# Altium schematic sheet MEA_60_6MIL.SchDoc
size A3; DocumentNumber: 1; SheetNumber: 1; SheetTotal: 1
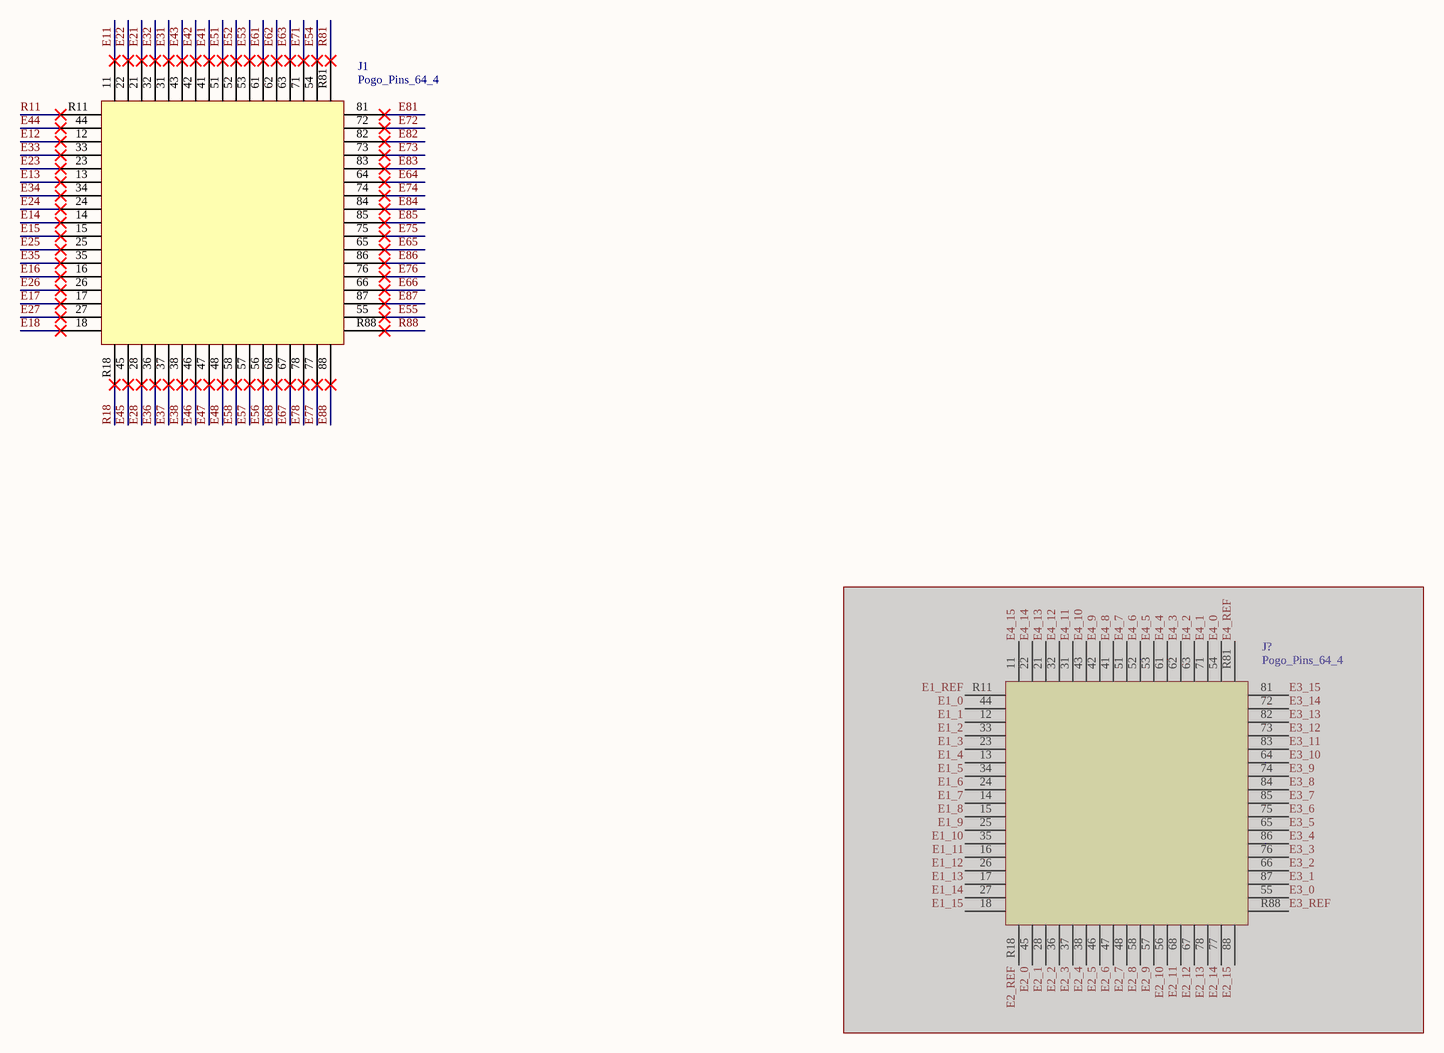
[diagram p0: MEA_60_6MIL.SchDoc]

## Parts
J1  Pogo_Pins_64_4  [Pogo_Pins_64_4]
J?  Pogo_Pins_64_4  [Pogo_Pins_64_4]  (masked out: inside a compile mask, not in the netlist)

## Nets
E11: J1.11
E12: J1.12
E13: J1.13
E14: J1.14
E15: J1.15
E16: J1.16
E17: J1.17
E18: J1.18
E21: J1.21
E22: J1.22
E23: J1.23
E24: J1.24
E25: J1.25
E26: J1.26
E27: J1.27
E28: J1.28
E31: J1.31
E32: J1.32
E33: J1.33
E34: J1.34
E35: J1.35
E36: J1.36
E37: J1.37
E38: J1.38
E41: J1.41
E42: J1.42
E43: J1.43
E44: J1.44
E45: J1.45
E46: J1.46
E47: J1.47
E48: J1.48
E51: J1.51
E52: J1.52
E53: J1.53
E54: J1.54
E55: J1.55
E56: J1.56
E57: J1.57
E58: J1.58
E61: J1.61
E62: J1.62
E63: J1.63
E64: J1.64
E65: J1.65
E66: J1.66
E67: J1.67
E68: J1.68
E71: J1.71
E72: J1.72
E73: J1.73
E74: J1.74
E75: J1.75
E76: J1.76
E77: J1.77
E78: J1.78
E81: J1.81
E82: J1.82
E83: J1.83
E84: J1.84
E85: J1.85
E86: J1.86
E87: J1.87
E88: J1.88
R11: J1.R11
R18: J1.R18
R81: J1.R81
R88: J1.R88

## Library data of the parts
J1 J? = Pogo_Pins_64_4: Pogo pins, 64 recording electrodes, 4 reference electrodes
